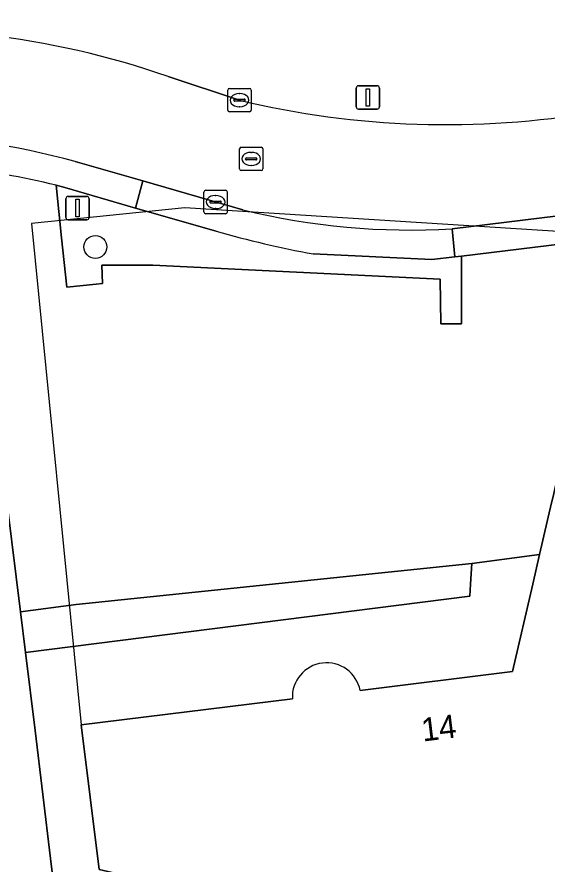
# Model space of a CAD drawing. Extents: x 161477 to 163040, y 383680 to 384871.
# Drawn here: x 161963.03 to 161985.69, y 383988.04 to 384024.24 of the extents above; entities that cross this region are included whole.
import ezdxf

# ---------------------------------------------------------------- set-up
doc = ezdxf.new("R2010")
doc.units = 0
for name, color, linetype in [('IMGEO_Berm_groen', 7, 'Continuous'), ('IMGEO_Boom', 7, 'Continuous'), ('IMGEO_Erf', 7, 'Continuous'), ('IMGEO_Groenvoorziening', 7, 'Continuous'), ('IMGEO_Kolk', 7, 'Continuous'), ('IMGEO_Lichtmast', 7, 'Continuous'), ('IMGEO_Pand', 7, 'Continuous'), ('IMGEO_Pand_nummerreeks', 7, 'Continuous'), ('IMGEO_Pand_overbouw', 7, 'Continuous'), ('IMGEO_Rijbaan_lokaal_gesloten', 7, 'Continuous'), ('IMGEO_Rijbaan_lokaal_open', 7, 'Continuous'), ('IMGEO_Rioolput', 7, 'Continuous'), ('IMGEO_Voetpad_open', 7, 'Continuous')]:
    doc.layers.add(name, color=color, linetype=linetype)

msp = doc.modelspace()

# ---------------------------------------------------------------- linework, layer by layer
at = {"layer": 'IMGEO_Berm_groen'}
msp.add_lwpolyline([(161969.486, 384021.696), (161972.542, 384020.685)], dxfattribs=at)
for centre, radius, start, end in [((161957.72, 383988.002), 35.689, 70.7507, 96.4837), ((161981.375, 384057.405), 37.767, 256.4746, 279.7582)]:
    msp.add_arc(centre, radius, start, end, dxfattribs=at)
at = {"layer": 'IMGEO_Boom'}
msp.add_circle((161966.381, 384014.412), 0.489, dxfattribs=at)
at = {"layer": 'IMGEO_Erf'}
for points in [[(161977.701, 383995.458), (161984.214, 383996.262), (161985.079, 384000), (161985.371, 384001.262), (161982.473, 384000.882), (161982.424, 384000), (161982.395, 383999.485), (161963.396, 383997.077), (161963.811, 383993.739), (161964.461, 383988.274), (161965.92, 383976.575), (161968.408, 383956.619), (161969.073, 383951.131), (161955.356, 383949.45), (161955.133, 383951.147)], [(161981.129, 383955.114), (161980.959, 383954.521), (161974.903, 383955.916), (161978.261, 383970.442), (161975.409, 383985.765), (161966.543, 383987.797), (161965.767, 383993.981), (161974.802, 383995.101)]]:
    msp.add_lwpolyline(points, dxfattribs=at)
msp.add_arc((161976.265, 383995.171), 1.465, 11.2833, 182.7575, dxfattribs=at)
at = {"layer": 'IMGEO_Groenvoorziening'}
msp.add_lwpolyline([(161971.545, 384015.089), (161968.099, 384016.067), (161965.069, 384016.953), (161964.705, 384017.045), (161964.939, 384014.793), (161965.157, 384012.69), (161966.417, 384012.822), (161966.691, 384012.851), (161966.65, 384013.634), (161968.843, 384013.634), (161981.124, 384013.033), (161981.148, 384011.125), (161982.035, 384011.125), (161982.035, 384013.634), (161982.035, 384013.809), (161982.034, 384014.017), (161981.753, 384013.983), (161980.764, 384013.87), (161975.695, 384014.111)], dxfattribs=at)
msp.add_arc((161983.206, 384055.277), 41.845, 253.8192, 259.6597, dxfattribs=at)
at = {"layer": 'IMGEO_Kolk'}
for p, q in [((161972.041, 384020.259), (161972.041, 384021.111)), ((161972.116, 384021.185), (161972.968, 384021.185)), ((161973.042, 384021.111), (161973.042, 384020.259)), ((161972.529, 384020.965), (161972.554, 384020.965)), ((161972.3, 384020.679), (161972.3, 384020.691)), ((161972.738, 384020.642), (161972.34, 384020.642)), ((161972.343, 384020.728), (161972.741, 384020.728)), ((161972.552, 384020.405), (161972.527, 384020.405)), ((161972.784, 384020.691), (161972.784, 384020.679)), ((161972.968, 384020.185), (161972.116, 384020.185)), ((161971.096, 384016.831), (161971.948, 384016.831)), ((161971.021, 384015.905), (161971.021, 384016.757)), ((161971.509, 384016.611), (161971.534, 384016.611)), ((161972.022, 384016.757), (161972.022, 384015.905)), ((161971.28, 384016.325), (161971.28, 384016.337)), ((161971.718, 384016.288), (161971.32, 384016.288)), ((161971.323, 384016.374), (161971.721, 384016.374)), ((161971.532, 384016.051), (161971.507, 384016.051)), ((161971.764, 384016.337), (161971.764, 384016.325)), ((161971.948, 384015.831), (161971.096, 384015.831))]:
    msp.add_line(p, q, dxfattribs=at)
for points in [[(161972.041, 384020.259), (161972.041, 384021.111)], [(161972.116, 384021.185), (161972.968, 384021.185)], [(161973.042, 384021.111), (161973.042, 384020.259)], [(161972.968, 384020.185), (161972.116, 384020.185)], [(161971.096, 384016.831), (161971.948, 384016.831)], [(161971.021, 384015.905), (161971.021, 384016.757)], [(161972.022, 384016.757), (161972.022, 384015.905)], [(161971.948, 384015.831), (161971.096, 384015.831)]]:
    msp.add_lwpolyline(points, dxfattribs=at)
for centre, radius, start, end in [((161972.118, 384021.109), 0.0765, 91.552, 178.448), ((161972.118, 384021.109), 0.0765, 91.552, 178.448), ((161972.966, 384021.109), 0.0765, 1.552, 88.448), ((161972.966, 384021.109), 0.0765, 1.552, 88.448), ((161972.34, 384020.688), 0.0403, 85.8775, 175.7526), ((161972.337, 384020.678), 0.0366, 178.938, 274.7102), ((161972.741, 384020.685), 0.043, 264.8664, 352.4533), ((161972.745, 384020.69), 0.0386, 1.7309, 96.639), ((161972.118, 384020.261), 0.0765, 181.552, 268.448), ((161972.118, 384020.261), 0.0765, 181.552, 268.448), ((161972.966, 384020.261), 0.0765, 271.552, 358.448), ((161972.966, 384020.261), 0.0765, 271.552, 358.448), ((161971.098, 384016.755), 0.0765, 91.552, 178.448), ((161971.098, 384016.755), 0.0765, 91.552, 178.448), ((161971.946, 384016.755), 0.0765, 1.552, 88.448), ((161971.946, 384016.755), 0.0765, 1.552, 88.448), ((161971.32, 384016.334), 0.0403, 85.8775, 175.7526), ((161971.317, 384016.324), 0.0366, 178.938, 274.7102), ((161971.721, 384016.331), 0.043, 264.8664, 352.4533), ((161971.725, 384016.336), 0.0386, 1.7309, 96.639), ((161971.098, 384015.907), 0.0765, 181.552, 268.448), ((161971.098, 384015.907), 0.0765, 181.552, 268.448), ((161971.946, 384015.907), 0.0765, 271.552, 358.448), ((161971.946, 384015.907), 0.0765, 271.552, 358.448)]:
    msp.add_arc(centre, radius, start, end, dxfattribs=at)
for centre, major_axis, ratio, start_param, end_param in [((161972.528, 384020.685), (-0.387, 0.002), 0.722429, 4.712389, 7.853982), ((161972.553, 384020.685), (-0.39, 0.002), 0.717154, 1.570796, 4.712389), ((161971.508, 384016.331), (-0.387, 0.002), 0.722429, 4.712389, 7.853982), ((161971.533, 384016.331), (-0.39, 0.002), 0.717154, 1.570796, 4.712389)]:
    msp.add_ellipse(centre, major_axis=major_axis, ratio=ratio, start_param=start_param, end_param=end_param, dxfattribs=at)
at = {"layer": 'IMGEO_Lichtmast'}
for p, q in [((161977.532, 384020.399), (161977.532, 384021.199)), ((161977.532, 384021.199), (161977.532, 384020.399)), ((161977.632, 384021.299), (161978.422, 384021.299)), ((161978.422, 384021.299), (161977.632, 384021.299)), ((161978.522, 384021.199), (161978.522, 384020.399)), ((161978.522, 384020.399), (161978.522, 384021.199)), ((161978.422, 384020.299), (161977.632, 384020.299)), ((161977.632, 384020.299), (161978.422, 384020.299)), ((161965.123, 384015.672), (161965.123, 384016.472)), ((161965.123, 384016.472), (161965.123, 384015.672)), ((161965.223, 384016.572), (161966.013, 384016.572)), ((161966.013, 384016.572), (161965.223, 384016.572)), ((161966.113, 384016.472), (161966.113, 384015.672)), ((161966.113, 384015.672), (161966.113, 384016.472)), ((161966.013, 384015.572), (161965.223, 384015.572)), ((161965.223, 384015.572), (161966.013, 384015.572))]:
    msp.add_line(p, q, dxfattribs=at)
for points in [[(161977.952, 384021.174), (161978.102, 384021.174), (161978.102, 384020.424), (161977.952, 384020.424), (161977.952, 384021.174)], [(161965.543, 384016.447), (161965.693, 384016.447), (161965.693, 384015.697), (161965.543, 384015.697), (161965.543, 384016.447)]]:
    msp.add_lwpolyline(points, dxfattribs=at)
for centre, start, end in [((161977.632, 384021.199), 90, 180), ((161977.632, 384021.199), 90, 180), ((161978.422, 384021.199), 0, 90), ((161978.422, 384021.199), 360, 90), ((161977.632, 384020.399), 180, 270), ((161977.632, 384020.399), 180, 270), ((161978.422, 384020.399), 270, 0), ((161978.422, 384020.399), 270, 0), ((161965.223, 384016.472), 90, 180), ((161965.223, 384016.472), 90, 180), ((161966.013, 384016.472), 0, 90), ((161966.013, 384016.472), 360, 90), ((161965.223, 384015.672), 180, 270), ((161965.223, 384015.672), 180, 270), ((161966.013, 384015.672), 270, 0), ((161966.013, 384015.672), 270, 0)]:
    msp.add_arc(centre, 0.1, start, end, dxfattribs=at)
at = {"layer": 'IMGEO_Pand'}
for points in [[(161964.461, 383988.274), (161963.811, 383993.739), (161963.396, 383997.077), (161963.181, 383998.816), (161962.423, 384004.917), (161962.246, 384006.341), (161952.749, 384005.163)], [(161992.411, 383998.745), (161992.257, 384000), (161991.801, 384003.707), (161991.454, 384003.664), (161991.48, 384003.456), (161986.327, 384003.735), (161986.378, 384003.925), (161986.011, 384004.007), (161985.946, 384003.746), (161985.88, 384003.477), (161985.371, 384001.262), (161985.079, 384000), (161984.214, 383996.262), (161977.701, 383995.458)], [(161949.098, 384000.565), (161949.412, 383998.153), (161949.604, 383996.676), (161950.476, 383989.986), (161944.534, 383989.254), (161939.601, 383988.646), (161939.204, 383988.597), (161939.001, 383990.24), (161919.858, 383987.878), (161922.541, 383965.891), (161923.153, 383960.88), (161924.788, 383947.478), (161955.119, 383951.24), (161955.133, 383951.147), (161955.356, 383949.45), (161969.073, 383951.131), (161968.408, 383956.619), (161965.92, 383976.575), (161964.461, 383988.274)], [(161974.802, 383995.101), (161965.767, 383993.981), (161966.543, 383987.797), (161975.409, 383985.765), (161978.261, 383970.442), (161974.903, 383955.916), (161980.959, 383954.521), (161981.129, 383955.114)]]:
    msp.add_lwpolyline(points, dxfattribs=at)
msp.add_arc((161976.265, 383995.171), 1.465, 11.2833, 182.7575, dxfattribs=at)
at = {"layer": 'IMGEO_Pand_overbouw'}
for points in [[(161977.701, 383995.458), (161984.214, 383996.262), (161985.079, 384000), (161985.371, 384001.262), (161985.88, 384003.477), (161985.946, 384003.746), (161986.011, 384004.007), (161986.378, 384003.925), (161986.327, 384003.735), (161991.48, 384003.456), (161991.454, 384003.664), (161991.801, 384003.707), (161991.39, 384006.662), (161991.261, 384007.832), (161991.117, 384009.147), (161990.439, 384014.803), (161970.21, 384016.077), (161963.654, 384015.417)], [(161963.654, 384015.417), (161965.767, 383993.981), (161974.802, 383995.101)]]:
    msp.add_lwpolyline(points, dxfattribs=at)
msp.add_arc((161976.265, 383995.171), 1.465, 11.2833, 182.7575, dxfattribs=at)
at = {"layer": 'IMGEO_Rijbaan_lokaal_gesloten'}
for points in [[(161981.63, 384015.178), (161994.527, 384016.771), (162120.907, 384032.335), (162136.714, 384034.256), (162236.067, 384046.546)], [(161972.542, 384020.685), (161969.486, 384021.696)], [(161965.511, 384018.06), (161968.407, 384017.239), (161972.68, 384015.993)]]:
    msp.add_lwpolyline(points, dxfattribs=at)
for centre, radius, start, end in [((161957.72, 383988.002), 35.689, 70.7507, 96.4837), ((161981.375, 384057.405), 37.767, 256.4746, 279.7582), ((161956.72, 383986.183), 33.067, 74.5816, 88.3289), ((161979.916, 384045.901), 30.771, 256.3999, 273.194)]:
    msp.add_arc(centre, radius, start, end, dxfattribs=at)
at = {"layer": 'IMGEO_Rijbaan_lokaal_open'}
for points in [[(161994.043, 384015.479), (161982.034, 384014.017), (161982.035, 384013.809), (161982.035, 384013.634), (161982.035, 384011.125), (161981.148, 384011.125), (161981.124, 384013.033), (161968.843, 384013.634), (161966.65, 384013.634), (161966.691, 384012.851), (161966.417, 384012.822), (161965.157, 384012.69), (161964.939, 384014.793), (161964.705, 384017.045)], [(161952.749, 384005.163), (161962.246, 384006.341), (161962.423, 384004.917), (161963.181, 383998.816), (161965.556, 383999.127), (161982.473, 384000.882), (161985.371, 384001.262), (161985.88, 384003.477), (161985.946, 384003.746), (161986.011, 384004.007), (161986.659, 384006.909), (161986.927, 384008.042), (161987.23, 384009.325), (161987.644, 384009.227), (161987.93, 384010.387), (161990.476, 384010.279), (161990.687, 384009.099), (161991.117, 384009.147), (161991.058, 384011.902)]]:
    msp.add_lwpolyline(points, dxfattribs=at)
msp.add_arc((161957.082, 383986.276), 31.699, 76.0849, 84.1116, dxfattribs=at)
at = {"layer": 'IMGEO_Rioolput'}
for p, q in [((161972.543, 384017.747), (161972.543, 384018.599)), ((161972.618, 384018.673), (161973.47, 384018.673)), ((161973.544, 384018.599), (161973.544, 384017.747)), ((161972.845, 384018.216), (161973.243, 384018.216)), ((161973.031, 384018.453), (161973.056, 384018.453)), ((161972.802, 384018.167), (161972.802, 384018.179)), ((161973.24, 384018.13), (161972.842, 384018.13)), ((161973.054, 384017.893), (161973.029, 384017.893)), ((161973.286, 384018.179), (161973.286, 384018.167)), ((161973.47, 384017.673), (161972.618, 384017.673))]:
    msp.add_line(p, q, dxfattribs=at)
for points in [[(161972.543, 384017.747), (161972.543, 384018.599)], [(161972.618, 384018.673), (161973.47, 384018.673)], [(161973.544, 384018.599), (161973.544, 384017.747)], [(161973.47, 384017.673), (161972.618, 384017.673)]]:
    msp.add_lwpolyline(points, dxfattribs=at)
for centre, radius, start, end in [((161972.62, 384018.597), 0.0765, 91.552, 178.448), ((161972.62, 384018.597), 0.0765, 91.552, 178.448), ((161973.468, 384018.597), 0.0765, 1.552, 88.448), ((161973.468, 384018.597), 0.0765, 1.552, 88.448), ((161972.842, 384018.176), 0.0403, 85.8775, 175.7526), ((161973.247, 384018.178), 0.0386, 1.7309, 96.639), ((161972.839, 384018.166), 0.0366, 178.938, 274.7102), ((161973.243, 384018.173), 0.043, 264.8664, 352.4533), ((161972.62, 384017.749), 0.0765, 181.552, 268.448), ((161972.62, 384017.749), 0.0765, 181.552, 268.448), ((161973.468, 384017.749), 0.0765, 271.552, 358.448), ((161973.468, 384017.749), 0.0765, 271.552, 358.448)]:
    msp.add_arc(centre, radius, start, end, dxfattribs=at)
for centre, major_axis, ratio, start_param, end_param in [((161973.03, 384018.173), (-0.387, 0.002), 0.722429, 4.712389, 7.853982), ((161973.055, 384018.173), (-0.39, 0.002), 0.717154, 1.570796, 4.712389)]:
    msp.add_ellipse(centre, major_axis=major_axis, ratio=ratio, start_param=start_param, end_param=end_param, dxfattribs=at)
at = {"layer": 'IMGEO_Voetpad_open'}
for points in [[(161964.705, 384017.045), (161965.069, 384016.953), (161968.099, 384016.067), (161968.407, 384017.239), (161965.511, 384018.06)], [(161972.68, 384015.993), (161968.407, 384017.239), (161968.099, 384016.067), (161971.545, 384015.089)], [(161975.695, 384014.111), (161980.764, 384013.87), (161981.753, 384013.983), (161981.63, 384015.178)]]:
    msp.add_lwpolyline(points, dxfattribs=at)
for points in [[(161994.043, 384015.479), (161994.665, 384015.555), (161994.527, 384016.771), (161981.63, 384015.178), (161981.753, 384013.983), (161982.034, 384014.017)], [(161982.395, 383999.485), (161982.424, 384000), (161982.473, 384000.882), (161965.556, 383999.127), (161963.181, 383998.816), (161963.396, 383997.077)]]:
    msp.add_lwpolyline(points, close=True, dxfattribs=at)
for centre, radius, start, end in [((161956.72, 383986.183), 33.067, 74.5816, 88.3289), ((161957.082, 383986.276), 31.699, 76.0849, 84.1116), ((161979.916, 384045.901), 30.771, 256.3999, 273.194), ((161983.206, 384055.277), 41.845, 253.8192, 259.6597)]:
    msp.add_arc(centre, radius, start, end, dxfattribs=at)

# ---------------------------------------------------------------- texts
at = {"layer": 'IMGEO_Pand_nummerreeks'}
msp.add_text('14', height=1, rotation=7.0359, dxfattribs=at).set_placement((161980.383, 383993.27))

doc.saveas('drawing.dxf')
